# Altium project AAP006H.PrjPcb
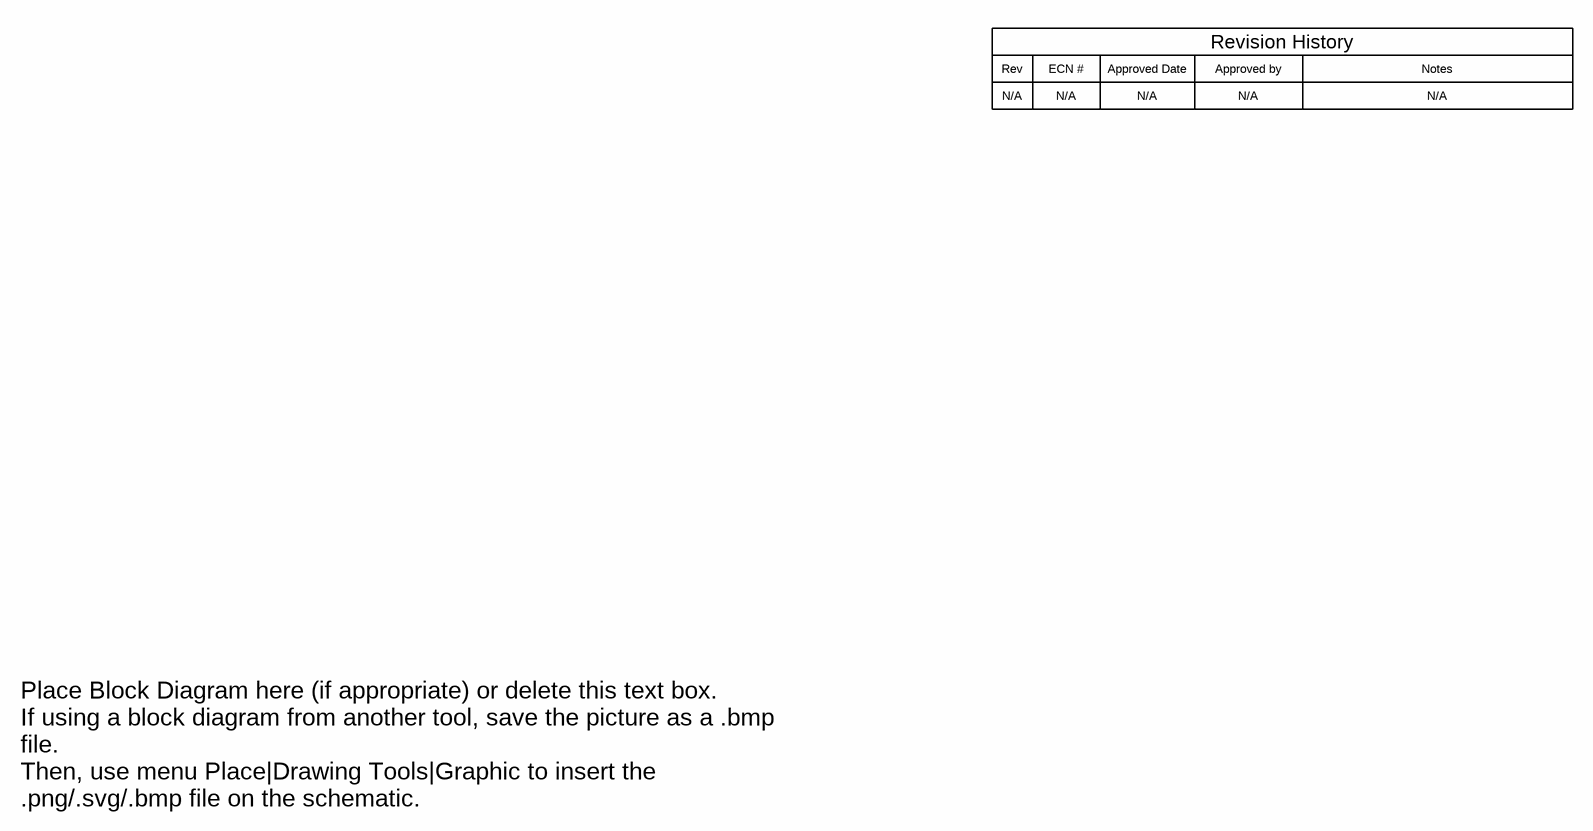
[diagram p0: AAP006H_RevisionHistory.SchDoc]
EVM_Orderable: PP-CMB-EVM; TID: N/A; TechSupport: http://www.ti.com/support; SCH_Rev: H; PRJ_Title: Pure Path Console MotherBoard; PRJ_Number: AAP006; PRJ_Engineer: CODY DOWLING; PRJ_Customer: Public Release; PCB_Rev: H; PCB_Layout: LDN; CopyrightYear: 2017
13 sheets, 94 parts. Net scope: flat (ports and power ports of the same name join across sheets).
Board file: AAP006H_PCB.PcbDoc
Sheets:
  AAP006H_RevisionHistory.SchDoc
  AAP006H_BlockDiagram.SchDoc
  AAP006H_USB.SchDoc
  AAP006H_SPDIF.SchDoc
  AAP006H_Codec1_PCM3168A.SchDoc
  AAP006H_Codec2_AIC3262.SchDoc
  AAP006H_PWM-Modulator.SchDoc
  AAP006H_MSP430.SchDoc
  AAP006H_IO-Expander.SchDoc
  AAP006H_MainConnector.SchDoc
  AAP006H_PowerSupplies.SchDoc
  AAP006H_StandoffHardware.SchDoc
  AAP006H_EVM_Hardware.SchDoc

## Sheet AAP006H_RevisionHistory.SchDoc
size 431 x 279 mm; Date: Not shown in title block; ApprovedBy: Not shown in title block; CheckedBy: Not shown in title block; Author: Not shown in title block; CompanyName: Not shown in title block; Engineer: Not shown in title block; Organization: Not shown in title block; Address1: Not shown in title block; Address2: Not shown in title block; Address3: Not shown in title block; Address4: Not shown in title block; DocumentNumber: 1; Revision: Use project parameter SCH_Rev; SheetNumber: 1; SheetTotal: 13; PageSetup: Record=PageOptions¦CenterHorizontal=True¦CenterVertical=True¦PrintScale=1.00¦XCorrection=1.00¦YCorrection=1.00¦PrintKind=0¦BorderSize=5000000¦LeftOffset=0¦BottomOffset=0¦Orientation=2¦PaperLength=1000¦PaperWidth=1000¦Scale=100¦PaperSource=15¦PrintQuality=600¦MediaType=1¦DitherType=10¦PaperKind=Letter¦PrintScaleMode=1

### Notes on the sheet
- Rev
- N/A
- ECN #
- Approved Date
- Approved by
- Revision History
- Notes
- Place Block Diagram here (if appropriate) or delete this text box.
  If using a block diagram from another tool, save the picture as a .bmp file.
  Then, use menu Place|Drawing Tools|Graphic to insert the .png/.svg/.bmp file on the schematic.

## Sheet AAP006H_BlockDiagram.SchDoc
size 431 x 279 mm; Date: Not shown in title block; ApprovedBy: Not shown in title block; CheckedBy: Not shown in title block; Author: Not shown in title block; CompanyName: Not shown in title block; Engineer: Not shown in title block; Organization: Not shown in title block; Address1: Not shown in title block; Address2: Not shown in title block; Address3: Not shown in title block; Address4: Not shown in title block; DocumentNumber: 2; Revision: Use project parameter SCH_Rev; SheetNumber: 2; SheetTotal: 13; PageSetup: Record=PageOptions¦CenterHorizontal=True¦CenterVertical=True¦PrintScale=1.00¦XCorrection=1.00¦YCorrection=1.00¦PrintKind=0¦BorderSize=5000000¦LeftOffset=0¦BottomOffset=0¦Orientation=2¦PaperLength=1000¦PaperWidth=1000¦Scale=100¦PaperSource=15¦PrintQuality=600¦MediaType=1¦DitherType=10¦PaperKind=Letter¦PrintScaleMode=1
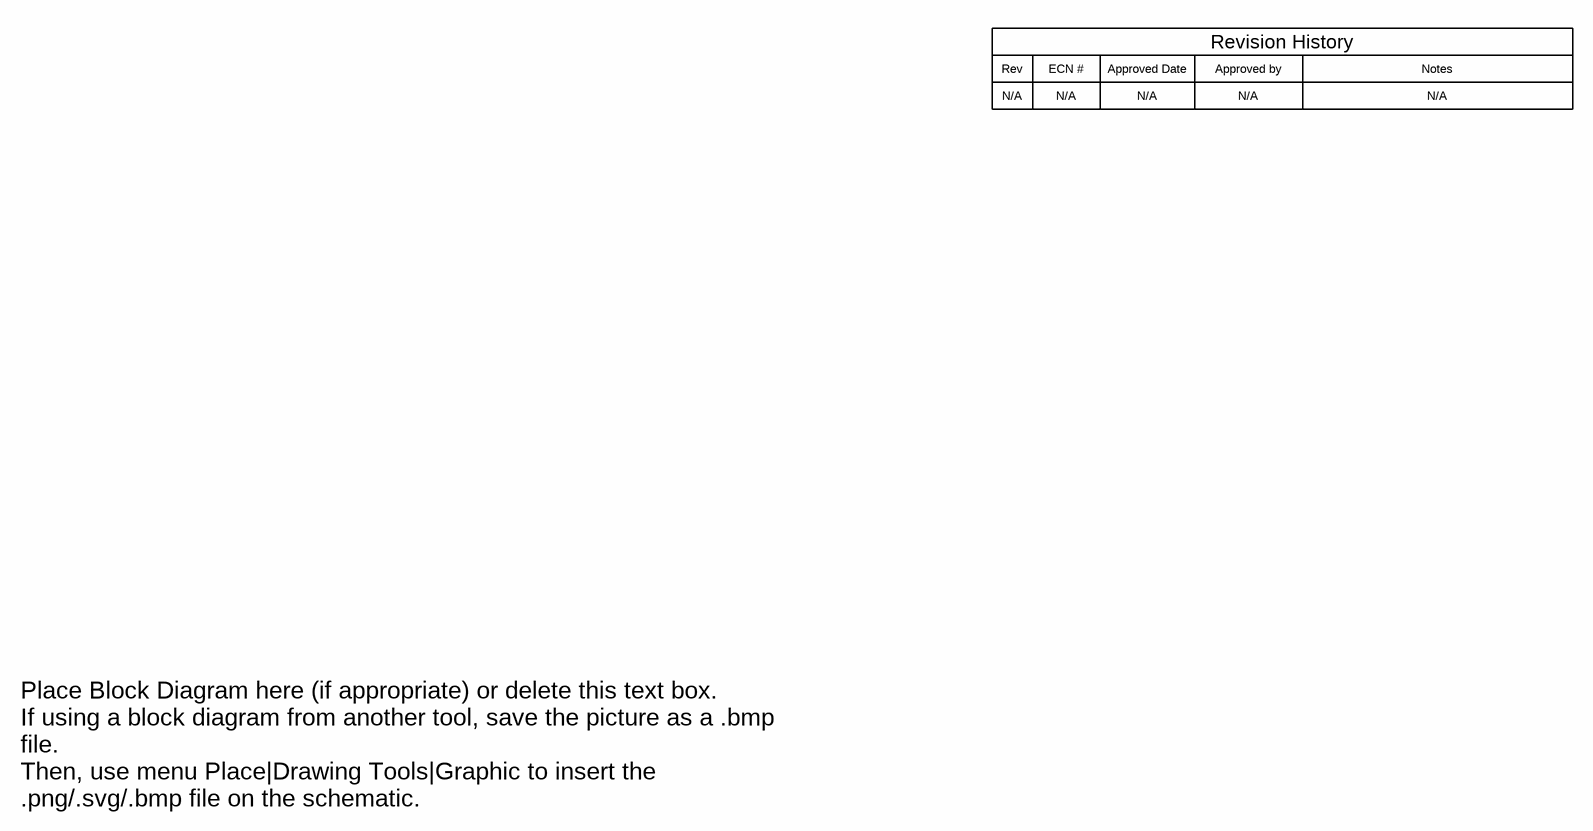
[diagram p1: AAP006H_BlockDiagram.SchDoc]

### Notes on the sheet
- Rev
- N/A
- ECN #
- Approved Date
- Approved by
- Revision History
- Notes
- Place Block Diagram here (if appropriate) or delete this text box.
  If using a block diagram from another tool, save the picture as a .bmp file.
  Then, use menu Place|Drawing Tools|Graphic to insert the .png/.svg/.bmp file on the schematic.

## Sheet AAP006H_USB.SchDoc: USB I/O
size 538 x 342 mm; Date: Not shown in title block; ApprovedBy: Not shown in title block; CheckedBy: Not shown in title block; Author: Not shown in title block; CompanyName: Not shown in title block; DrawnBy: LDN; Engineer: Not shown in title block; Organization: Not shown in title block; Address1: Not shown in title block; Address2: Not shown in title block; Address3: Not shown in title block; Address4: Not shown in title block; DocumentNumber: 3; Revision: Use project parameter SCH_Rev; SheetNumber: 3; SheetTotal: 13; PageSetup: Record=PageOptions¦CenterHorizontal=True¦CenterVertical=True¦PrintScale=1.00¦XCorrection=1.00¦YCorrection=1.00¦PrintKind=0¦BorderSize=5000000¦LeftOffset=0¦BottomOffset=0¦Orientation=2¦PaperLength=1000¦PaperWidth=1000¦Scale=100¦PaperSource=15¦PrintQuality=600¦MediaType=1¦DitherType=10¦PaperKind=Letter¦PrintScaleMode=1
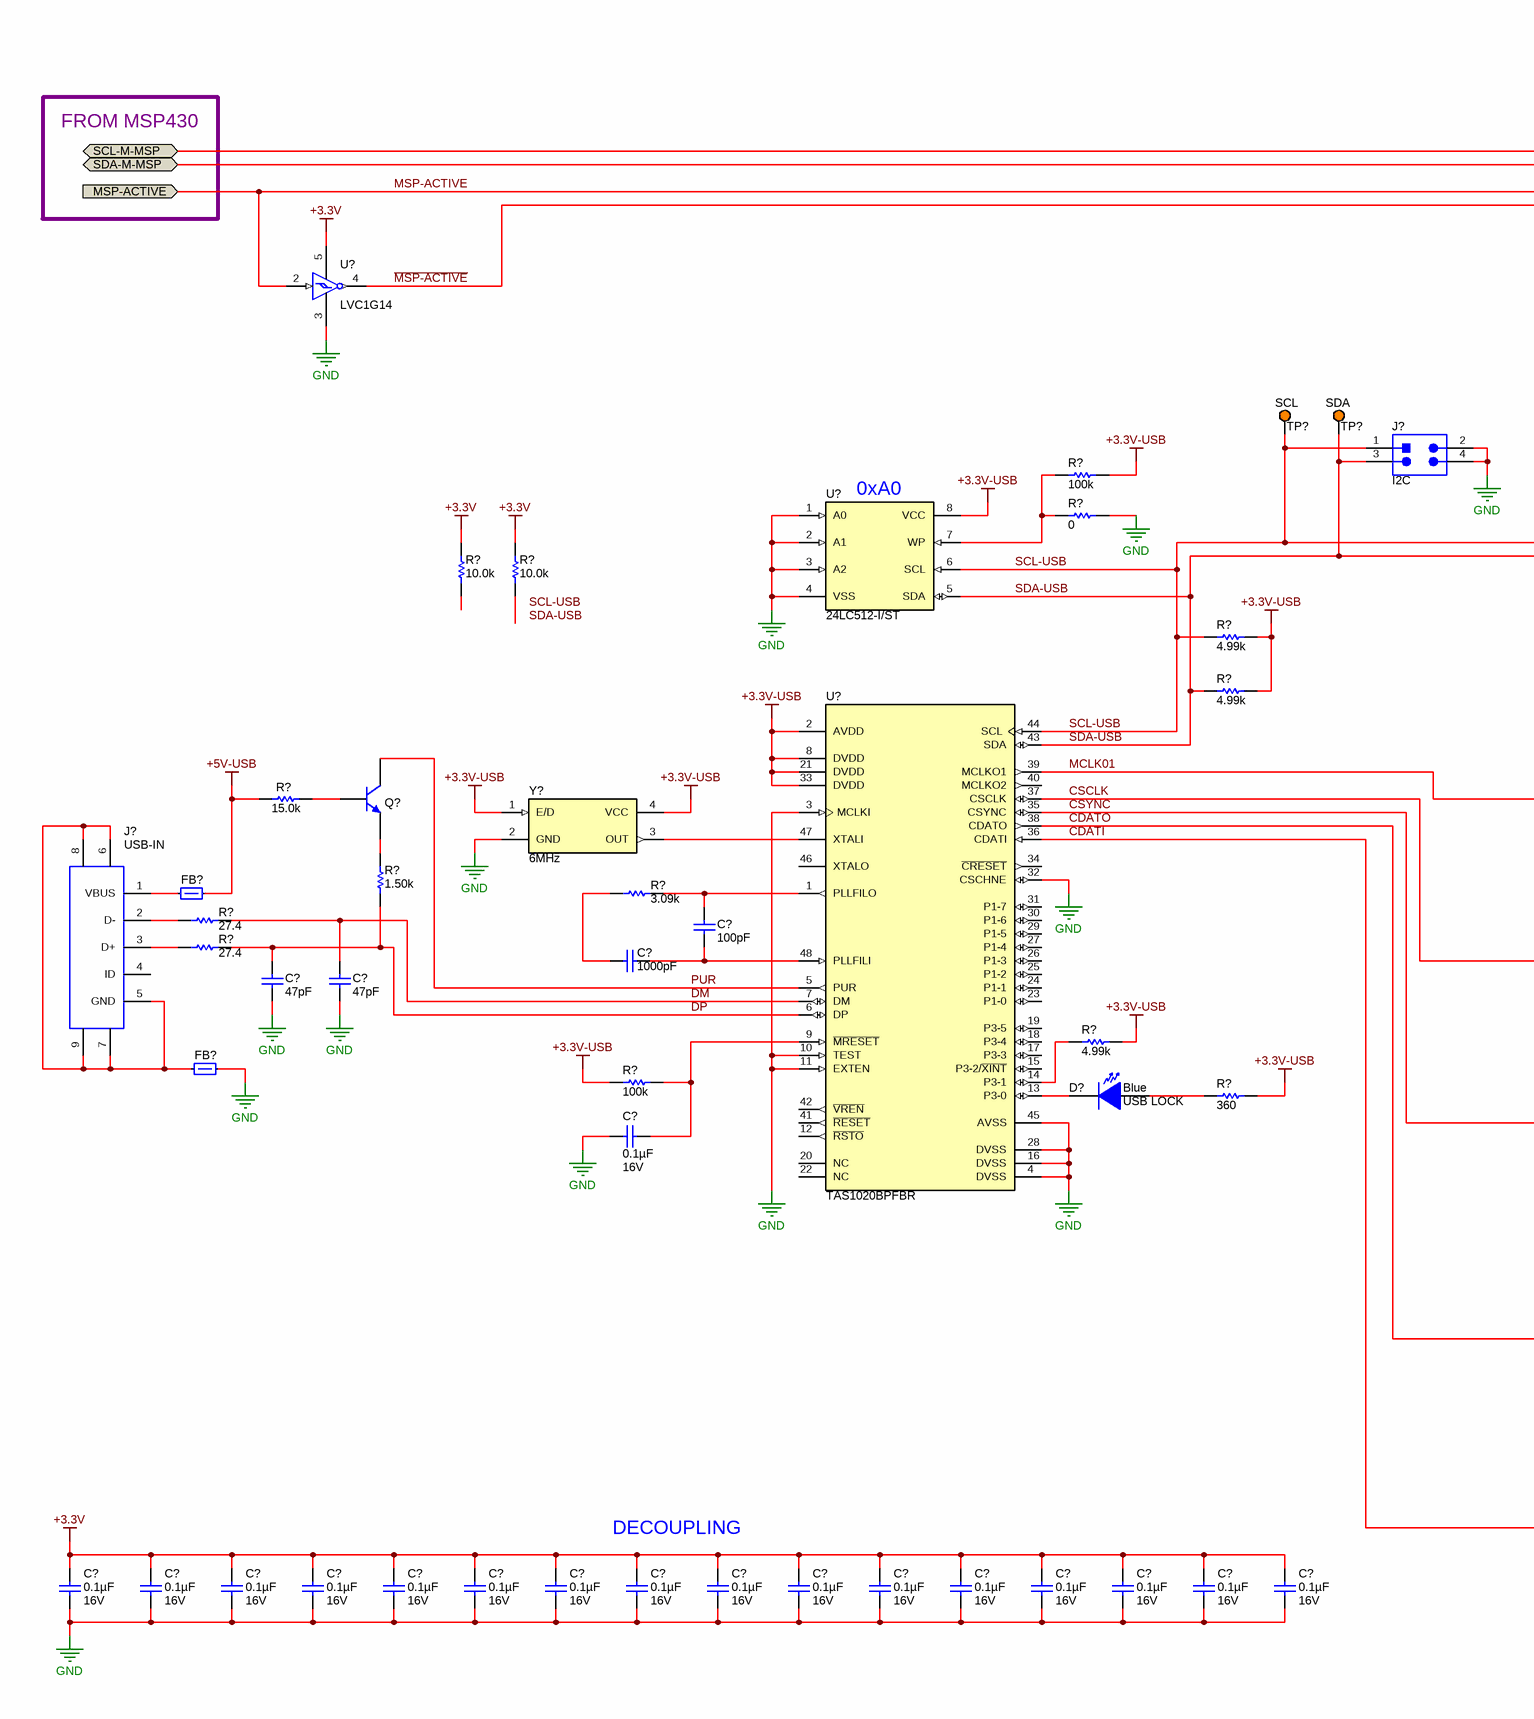
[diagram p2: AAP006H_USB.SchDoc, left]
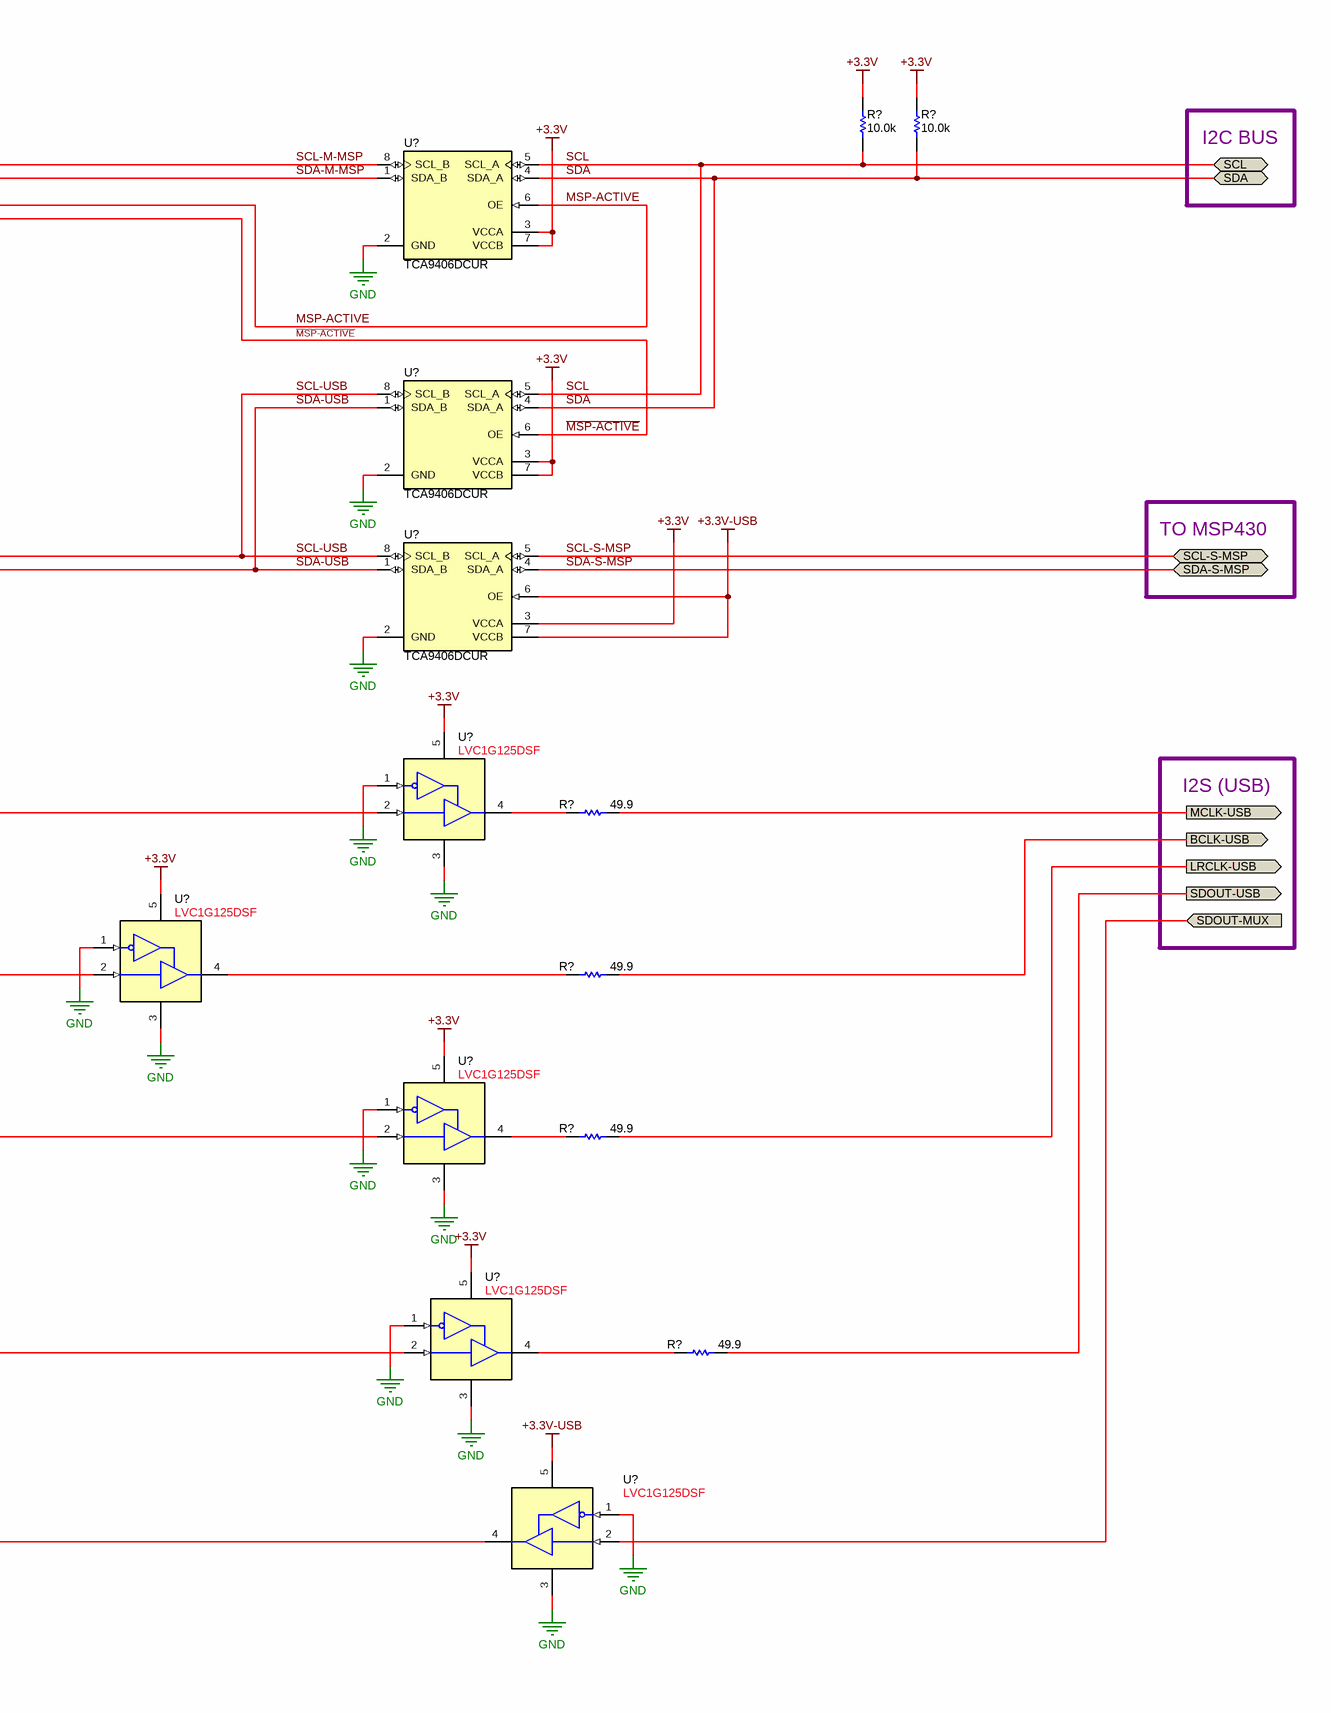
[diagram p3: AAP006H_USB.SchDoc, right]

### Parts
(Parts that share a designator on the sheet are numbered #1, #2 ... from top to bottom, then left to right.)
C?#1  ValueDisplayed: 100pF  [0402L]  (hidden comment: GRM1555C1H101JA01D)
C?#2  ValueDisplayed: 1000pF  [0402L]  (hidden comment: GRM1555C1H102JA01D)
C?#3  ValueDisplayed: 47pF  [0402L]  (hidden comment: GRM1555C1E470JA01D)
C?#4  ValueDisplayed: 47pF  [0402L]  (hidden comment: GRM1555C1E470JA01D)
C?#5  ValueDisplayed: 0.1µF  Value2: 16V  [0402L]  (hidden comment: GRM155R71C104KA88D)
C?#6  ValueDisplayed: 0.1µF  Value2: 16V  [0402L]  (hidden comment: GRM155R71C104KA88D)
C?#7  ValueDisplayed: 0.1µF  Value2: 16V  [0402L]  (hidden comment: GRM155R71C104KA88D)
C?#8  ValueDisplayed: 0.1µF  Value2: 16V  [0402L]  (hidden comment: GRM155R71C104KA88D)
C?#9  ValueDisplayed: 0.1µF  Value2: 16V  [0402L]  (hidden comment: GRM155R71C104KA88D)
C?#10  ValueDisplayed: 0.1µF  Value2: 16V  [0402L]  (hidden comment: GRM155R71C104KA88D)
C?#11  ValueDisplayed: 0.1µF  Value2: 16V  [0402L]  (hidden comment: GRM155R71C104KA88D)
C?#12  ValueDisplayed: 0.1µF  Value2: 16V  [0402L]  (hidden comment: GRM155R71C104KA88D)
C?#13  ValueDisplayed: 0.1µF  Value2: 16V  [0402L]  (hidden comment: GRM155R71C104KA88D)
C?#14  ValueDisplayed: 0.1µF  Value2: 16V  [0402L]  (hidden comment: GRM155R71C104KA88D)
C?#15  ValueDisplayed: 0.1µF  Value2: 16V  [0402L]  (hidden comment: GRM155R71C104KA88D)
C?#16  ValueDisplayed: 0.1µF  Value2: 16V  [0402L]  (hidden comment: GRM155R71C104KA88D)
C?#17  ValueDisplayed: 0.1µF  Value2: 16V  [0402L]  (hidden comment: GRM155R71C104KA88D)
C?#18  ValueDisplayed: 0.1µF  Value2: 16V  [0402L]  (hidden comment: GRM155R71C104KA88D)
C?#19  ValueDisplayed: 0.1µF  Value2: 16V  [0402L]  (hidden comment: GRM155R71C104KA88D)
C?#20  ValueDisplayed: 0.1µF  Value2: 16V  [0402L]  (hidden comment: GRM155R71C104KA88D)
C?#21  ValueDisplayed: 0.1µF  Value2: 16V  [0402L]  (hidden comment: GRM155R71C104KA88D)
D?  USB LOCK  value Blue  [LED_SMLP12_BLUE]
FB?#1  MPZ1608S221A  [0603L]  (value not drawn)
FB?#2  MPZ1608S221A  [0603L]  (value not drawn)
J?#1  I2C  [Sullins_PxC02DAAN]
J?#2  USB-IN  [CONN_USB_DX4R205JJA]
Q?  MMBT2222A  [SOT-23]  (value not drawn)
R?#1  value 10.0k  [0402L]  (hidden comment: CRCW040210K0FKED)
R?#2  value 10.0k  [0402L]  (hidden comment: CRCW040210K0FKED)
R?#3  value 100k  [0402L]  (hidden comment: CRCW0402100KFKED)
R?#4  ValueDisplayed: 0  [0603L]  (hidden comment: CRCW06030000Z0EA)
R?#5  ValueDisplayed: 10.0k  [0402L]  (hidden comment: CRCW040210K0FKED)
R?#6  ValueDisplayed: 10.0k  [0402L]  (hidden comment: CRCW040210K0FKED)
R?#7  value 4.99k  [0402L]  (hidden comment: CRCW04024K99FKED)
R?#8  value 4.99k  [0402L]  (hidden comment: CRCW04024K99FKED)
R?#9  value 15.0k  [0402L]  (hidden comment: CRCW040215K0FKED)
R?#10  value 49.9  [0402L]  (hidden comment: CRCW040249R9FKED)
R?#11  value 1.50k  [0402L]  (hidden comment: CRCW04021K50FKED)
R?#12  value 3.09k  [0402L]  (hidden comment: CRCW04023K09FKED)
R?#13  value 27.4  [0402L]  (hidden comment: CRCW040227R4FKED)
R?#14  value 27.4  [0402L]  (hidden comment: CRCW040227R4FKED)
R?#15  value 49.9  [0402L]  (hidden comment: CRCW040249R9FKED)
R?#16  value 4.99k  [0402L]  (hidden comment: CRCW04024K99FKED)
R?#17  value 100k  [0402L]  (hidden comment: CRCW0402100KFKED)
R?#18  value 360  [0402L]  (hidden comment: CRCW0402360RJNED)
R?#19  value 49.9  [0402L]  (hidden comment: CRCW040249R9FKED)
R?#20  value 49.9  [0402L]  (hidden comment: CRCW040249R9FKED)
TP?#1  SCL  [Keystone5003]
TP?#2  SDA  [Keystone5003]
U?#1  TCA9406DCUR  [DCU0008A_N]
U?#2  LVC1G14  [DRL0005A]
U?#3  TCA9406DCUR  [DCU0008A_N]
U?#4  TCA9406DCUR  [DCU0008A_N]
U?#5  24LC512-I/ST  [TSSOP-8]
U?#6  NewPartNumber: LVC1G125DSF  [DRL0005A]  (hidden comment: SN74LVC1G125DRLR)
U?#7  TAS1020BPFBR  [PFB0048A_N]
U?#8  NewPartNumber: LVC1G125DSF  [DRL0005A]  (hidden comment: SN74LVC1G125DRLR)
U?#9  NewPartNumber: LVC1G125DSF  [DRL0005A]  (hidden comment: SN74LVC1G125DRLR)
U?#10  NewPartNumber: LVC1G125DSF  [DRL0005A]  (hidden comment: SN74LVC1G125DRLR)
U?#11  NewPartNumber: LVC1G125DSF  [DRL0005A]  (hidden comment: SN74LVC1G125DRLR)
Y?  Frequency: 6MHz  [OSC_CTS_625]  (hidden comment: 625L3I006M00000)

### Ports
BCLK-USB (out), LRCLK-USB (out), MCLK-USB (out), MSP-ACTIVE (in), SCL (bidir), SCL-M-MSP (bidir), SCL-S-MSP (bidir), SDA (bidir), SDA-M-MSP (bidir), SDA-S-MSP (bidir), SDOUT-MUX (in), SDOUT-USB (out)

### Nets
+3.3V: C?#6.1 C?#7.1 C?#8.1 C?#9.1 C?#10.1 C?#11.1 C?#12.1 C?#13.1 C?#14.1 C?#15.1 C?#16.1 C?#17.1 C?#18.1 C?#19.1 C?#20.1 C?#21.1 R?#1.1 R?#2.1 R?#5.2 R?#6.2 U?#1.3(VCCA) U?#1.7(VCCB) U?#2.5(VCC) U?#3.3(VCCA) U?#3.7(VCCB) U?#4.3(VCCA) U?#6.5(VCC) U?#8.5(VCC) U?#9.5(VCC) U?#10.5(VCC)
+3.3V-USB: R?#3.2 R?#7.2 R?#8.2 R?#16.1 R?#17.1 R?#18.1 U?#4.6(OE) U?#4.7(VCCB) U?#5.8(VCC) U?#7.2(AVDD) U?#7.8(DVDD) U?#7.21(DVDD) U?#7.33(DVDD) U?#11.5(VCC) Y?.1(E/D) Y?.4(VCC)
+5V-USB: FB?#1.2 R?#9.1
GND: C?#3.1 C?#4.1 C?#5.1 C?#6.2 C?#7.2 C?#8.2 C?#9.2 C?#10.2 C?#11.2 C?#12.2 C?#13.2 C?#14.2 C?#15.2 C?#16.2 C?#17.2 C?#18.2 C?#19.2 C?#20.2 C?#21.2 FB?#2.2 J?#1.2 J?#1.4 R?#4.2 U?#1.2(GND) U?#2.3(GND) U?#3.2(GND) U?#4.2(GND) U?#5.1(A0) U?#5.2(A1) U?#5.3(A2) U?#5.4(VSS) U?#6.1(~{OE}) U?#6.3(GND) U?#7.3(MCLKI) U?#7.4(DVSS) U?#7.10(TEST) U?#7.11(EXTEN) U?#7.16(DVSS) U?#7.28(DVSS) U?#7.32(CSCHNE) U?#7.45(AVSS) U?#8.1(~{OE}) U?#8.3(GND) U?#9.1(~{OE}) U?#9.3(GND) U?#10.1(~{OE}) U?#10.3(GND) U?#11.1(~{OE}) U?#11.3(GND) Y?.2(GND)
~{MSP-ACTIVE}: U?#2.4(Y) U?#3.6(OE)
BCLK-USB: R?#15.2 ; port BCLK-USB
CDATI: U?#7.36(CDATI) U?#11.4(Y)
CDATO: U?#7.38(CDATO) U?#10.2(A)
CSCLK: U?#7.37(CSCLK) U?#8.2(A)
CSYNC: U?#7.35(CSYNC) U?#9.2(A)
DM: C?#4.2 R?#13.2 U?#7.7(DM)
DP: C?#3.2 R?#11.2 R?#14.2 U?#7.6(DP)
LRCLK-USB: R?#19.2 ; port LRCLK-USB
MCLK01: U?#6.2(A) U?#7.39(MCLKO1)
MCLK-USB: R?#10.2 ; port MCLK-USB
MSP-ACTIVE: U?#1.6(OE) U?#2.2(A) ; port MSP-ACTIVE
PUR: Q?.3(C) U?#7.5(PUR)
SCL: R?#1.2 U?#1.5(SCL_A) U?#3.5(SCL_A) ; port SCL
SCL-M-MSP: U?#1.8(SCL_B) ; port SCL-M-MSP
SCL-S-MSP: U?#4.5(SCL_A) ; port SCL-S-MSP
SCL-USB: J?#1.1 R?#7.1 TP?#1.1 U?#3.8(SCL_B) U?#4.8(SCL_B) U?#5.6(SCL) U?#7.44(SCL)
SDA: R?#2.2 U?#1.4(SDA_A) U?#3.4(SDA_A) ; port SDA
SDA-M-MSP: U?#1.1(SDA_B) ; port SDA-M-MSP
SDA-S-MSP: U?#4.4(SDA_A) ; port SDA-S-MSP
SDA-USB: J?#1.3 R?#8.1 TP?#2.1 U?#3.1(SDA_B) U?#4.1(SDA_B) U?#5.5(SDA) U?#7.43(SDA)
SDOUT-MUX: U?#11.2(A) ; port SDOUT-MUX
SDOUT-USB: R?#20.2 ; port SDOUT-USB
NetC?#1_1: C?#1.1 R?#12.2 U?#7.1(PLLFILO)
NetC?#1_2: C?#1.2 C?#2.1 U?#7.48(PLLFILI)
NetC?#2_2: C?#2.2 R?#12.1
NetC?#5_2: C?#5.2 R?#17.2 U?#7.9(~{MRESET})
NetD?_1: D?.1(A) R?#18.2
NetD?_2: D?.2(K) U?#7.13(P3-0)
NetFB?#1_1: FB?#1.1 J?#2.1(VBUS)
NetFB?#2_1: FB?#2.1 J?#2.5(GND) J?#2.6 J?#2.7 J?#2.8 J?#2.9
NetJ?#2_2: J?#2.2(D-) R?#13.1
NetJ?#2_3: J?#2.3(D+) R?#14.1
NetQ?_1: Q?.1(B) R?#9.2
NetQ?_2: Q?.2(E) R?#11.1
NetR?#3_1: R?#3.1 R?#4.1 U?#5.7(WP)
NetR?#10_1: R?#10.1 U?#6.4(Y)
NetR?#15_1: R?#15.1 U?#8.4(Y)
NetR?#16_2: R?#16.2 U?#7.14(P3-1)
NetR?#19_1: R?#19.1 U?#9.4(Y)
NetR?#20_1: R?#20.1 U?#10.4(Y)
NetU?#7_47: U?#7.47(XTALI) Y?.3(OUT)

Not connected (* = marked no-connect by the designer): J?#2 4(ID); R?#5 1; R?#6 1; U?#7 12(~{RSTO}) 15(P3-2/~{XINT}) 17(P3-3) 18(P3-4) 19(P3-5) 20(NC) 22(NC) 23(P1-0) 24(P1-1) 25(P1-2) 26(P1-3) 27(P1-4) 29(P1-5) 30(P1-6) 31(P1-7) 34(~{CRESET}) 40(MCLKO2) 41(~{RESET}) 42(~{VREN}) 46(XTALO)

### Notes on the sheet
- FROM MSP430
- I2C BUS
- (near U?#5) 0xA0
- TO MSP430
- I2S (USB)
- (near C?#13) DECOUPLING
- Labels drawn without touching a wire or pin: SCL-USB, SDA-USB

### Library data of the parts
C?#1 = GRM1555C1H101JA01D: CAP, CERM, 100pF, 50V, +/-5%, C0G/NP0, 0402; Manufacturer: MuRata; Polarized: N; CompType: Capacitor; U/M: EA; Cap_F: 0.0000000001; Tolerance_%: 5; Value1: Unknown; VDC_V: 50; TaMin_C: -55; TaMax_C: 125; Cap_Case: 0402
C?#2 = GRM1555C1H102JA01D: CAP, CERM, 1000pF, 50V, +/-5%, C0G/NP0, 0402; Manufacturer: MuRata; Polarized: N; CompType: Capacitor; U/M: EA; Cap_F: 0.000000001; Tolerance_%: 5; Value1: Unknown; VDC_V: 50; TaMin_C: -55; TaMax_C: 125; Cap_Case: 0402
C?#3 C?#4 = GRM1555C1E470JA01D: CAP, CERM, 47pF, 25V, +/-5%, C0G/NP0, 0402; Manufacturer: MuRata; Polarized: N; CompType: Capacitor; U/M: EA; Cap_F: 0.000000000047; Tolerance_%: 5; Value1: Unknown; VDC_V: 25; TaMin_C: -55; TaMax_C: 125; Cap_Case: 0402
C?#5-C?#21 = GRM155R71C104KA88D: CAP, CERM, 0.1uF, 16V, +/-10%, X7R, 0402; Manufacturer: MuRata; Polarized: N; CompType: Capacitor; U/M: EA; Cap_F: 0.0000001; Tolerance_%: 10; Value1: Unknown; VDC_V: 16; TaMin_C: -55; TaMax_C: 125; Cap_Case: 0402
D? = SMLP12BC7TT86: LED, Blue, SMD; Manufacturer: Rohm; Type: InGaN; Vf_V: 2.9; Value2: 2.9V; Io_A: 0.005; Tjmax_C: 85; Value1: W; U/M: EA
FB?#1 FB?#2 = MPZ1608S221A: 2.2A Ferrite Bead, 220 ohm @ 100MHz, SMD; Manufacturer: TDK; Value: 220 ohm; Imax_A: 2.2; DCR_ohm: 0.05; Value1: 0.05 ohm; ZTyp@100MHz_Ohm: 220; U/M: EA
J?#1 = PBC02DAAN: Header, 2.54mm, 2x2, Gold, TH; Manufacturer: Sullins Connector Solutions; SymbolCreator: a0412235; Pitch_mm: 2.54; Gender: Male; Shrouded: N; Row_Count: 2; Current_A: 3; Voltage_V: 1800; Cert_UL: Y
J?#2 = DX4R205JJAR1800: Connector, Receptacle, Micro-USB Type AB, R/A, Bottom Mount SMT; Manufacturer: JAE Electronics; SymbolCreator: a0799628; U/M: EA
Q? = MMBT2222A, Fairchild Semiconductor: Transistor, NPN, 40V, 0.15A, SOT-23; CompType: BJT; PNP: 0; NPN: 1; Vceo_V: 40; Vcesat1_V: 0.3; Value: 0.3V; IcRated_A: 0.15; HfeMax: 300; TaMin_C: -55; TaMax_C: 150; U/M: EA
R?#1 R?#2 = CRCW040210K0FKED: RES, 10.0k ohm, 1%, 0.063W, 0402; Manufacturer: Vishay-Dale; CompType: Resistor; Res_ohm: 10000; Value_Code: 10k0; Tolerance_%: 1; Power_W: 0.063; VDC_V: 50; TempCo: 100 ppm/C; EIA_Code: E96; U/M: EA
R?#3 R?#17 = CRCW0402100KFKED: RES, 100k ohm, 1%, 0.063W, 0402; Manufacturer: Vishay-Dale; CompType: Resistor; Res_ohm: 100000; Tolerance_%: 1; Power_W: 0.063; VDC_V: 50; TempCo: 100 ppm/C; EIA_Code: E96; U/M: EA
R?#4 = CRCW06030000Z0EA: RES, 0, 5%, 0.1 W, 0603; Manufacturer: Vishay-Dale; CompType: Resistor; Value: 0; Value_Code: 0000; Tolerance_%: 5; Power_W: 0.1; Value2: 0.1W; VDC_V: 75; TempCo: 200 ppm/C; EIA_Code: E24; U/M: EA
R?#5 R?#6 = CRCW040210K0FKED: RES, 10.0 k, 1%, 0.063 W, 0402; Manufacturer: Vishay-Dale; CompType: Resistor; Value: 10.0k; Res_ohm: 10000; Value_Code: 10k0; Tolerance_%: 1; Power_W: 0.063; Value2: 0.063W; VDC_V: 50; TempCo: 100 ppm/C; EIA_Code: E96; U/M: EA
R?#7 R?#8 R?#16 = CRCW04024K99FKED: RES, 4.99k ohm, 1%, 0.063W, 0402; Manufacturer: Vishay-Dale; CompType: Resistor; Res_ohm: 4990; Value_Code: 4k99; Tolerance_%: 1; Power_W: 0.063; VDC_V: 50; TempCo: 100 ppm/C; EIA_Code: E96; U/M: EA
R?#9 = CRCW040215K0FKED: RES, 15.0k ohm, 1%, 0.063W, 0402; Manufacturer: Vishay-Dale; CompType: Resistor; Res_ohm: 15000; Value_Code: 15k0; Tolerance_%: 1; Power_W: 0.063; VDC_V: 50; TempCo: 100 ppm/C; EIA_Code: E96; U/M: EA
R?#10 R?#15 R?#19 R?#20 = CRCW040249R9FKED: RES, 49.9 ohm, 1%, 0.063W, 0402; Manufacturer: Vishay-Dale; CompType: Resistor; Value_Code: 49R9; Tolerance_%: 1; Power_W: 0.063; VDC_V: 50; TempCo: 100 ppm/C; EIA_Code: E96; U/M: EA
R?#11 = CRCW04021K50FKED: RES, 1.50k ohm, 1%, 0.063W, 0402; Manufacturer: Vishay-Dale; CompType: Resistor; Res_ohm: 1500; Value_Code: 1k50; Tolerance_%: 1; Power_W: 0.063; VDC_V: 50; TempCo: 100 ppm/C; EIA_Code: E96; U/M: EA
R?#12 = CRCW04023K09FKED: RES, 3.09k ohm, 1%, 0.063W, 0402; Manufacturer: Vishay-Dale; CompType: Resistor; Res_ohm: 3090; Value_Code: 3k09; Tolerance_%: 1; Power_W: 0.063; VDC_V: 50; TempCo: 100 ppm/C; EIA_Code: E96; U/M: EA
R?#13 R?#14 = CRCW040227R4FKED: RES, 27.4 ohm, 1%, 0.063W, 0402; Manufacturer: Vishay-Dale; CompType: Resistor; Value_Code: 27R4; Tolerance_%: 1; Power_W: 0.063; VDC_V: 50; TempCo: 100 ppm/C; EIA_Code: E96; U/M: EA
R?#18 = CRCW0402360RJNED: RES, 360 ohm, 5%, 0.063W, 0402; Manufacturer: Vishay-Dale; CompType: Resistor; Value_Code: 360R; Tolerance_%: 5; Power_W: 0.063; VDC_V: 50; TempCo: 200 ppm/C; EIA_Code: E24; U/M: EA
TP?#1 TP?#2 = 5003: Test Point, Miniature, Orange, TH; Manufacturer: Keystone; CompType: Test Point Loop; U/M: EA
U?#1 U?#3 U?#4 = TCA9406DCUR: TCA9406 Dual Bidirectional 1-MHz I2C-BUS and SMBus Voltage Level-Translator, 1.65 to 3.6 V, -40 to 85 degC, 8-pin US8 (DCU), Green (RoHS & no Sb/Br); Manufacturer: Texas Instruments; Alternate PartNumber: Equivalent; SubFamily: I2C Special Function; No. of Outputs: 2; VCC(Min)(V): -0.5; VCC(Max)(V): 4.6; Max Frequency(kHz): 1000; Function: I2C Voltage Level Translator; Enable Pin: Yes; Rating: Catalog
U?#2 = SN74LVC1G14DRLR: SINGLE SCHMITT-TRIGGER INVERTER, DRL0005A (SOT-5); Manufacturer: Texas Instruments; SymbolCreator: a0799628; SizeArea_mm2: 2.56; SizeAreaWB_mm2: 6.76; SizeX_mm: 1.6; SizeZ_mm: 0.6; CompType: IC; U/M: EA
U?#5 = 24LC512-I/ST: EEPROM, 512KBIT, 400KHZ, 8TSSOP; Manufacturer: Microchip; SymbolCreator: a0411947; SizeAreaWB_mm2: 42; SizeArea_mm2: 19.2; SizeX_mm: 6.4; SizeY_mm: 3; SizeZ_mm: 1.2
U?#6 U?#8-U?#11 = SN74LVC1G125DRLR: Single Bus Buffer Gate With 3-State Output, DRL0005A (SOT-5); Manufacturer: Texas Instruments; SymbolCreator: Altium; SizeArea_mm2: 2.56; SizeAreaWB_mm2: 6.76; SizeX_mm: 1.6; SizeZ_mm: 0.6; CompType: IC; U/M: EA
U?#7 = TAS1020BPFBR: USB Streaming Controller, PFB0048A, NRND; Manufacturer: Texas Instruments; SymbolCreator: Altium; CompType: IC; U/M: EA
Y? = 625L3I006M00000: Oscillator, 6MHz, 3.3V, SMD; Manufacturer: CTS Electrocomponents; SymbolCreator: a0411947; U/M: EA; TaMin_C: -40; TaMax_C: 85; Frequency Stability: ±50ppm

## Sheet AAP006H_SPDIF.SchDoc
size 431 x 279 mm; Date: Not shown in title block; ApprovedBy: Not shown in title block; CheckedBy: Not shown in title block; Author: Not shown in title block; CompanyName: Not shown in title block; Engineer: Not shown in title block; Organization: Not shown in title block; Address1: Not shown in title block; Address2: Not shown in title block; Address3: Not shown in title block; Address4: Not shown in title block; DocumentNumber: 4; Revision: Use project parameter SCH_Rev; SheetNumber: 4; SheetTotal: 13; PageSetup: Record=PageOptions¦CenterHorizontal=True¦CenterVertical=True¦PrintScale=1.00¦XCorrection=1.00¦YCorrection=1.00¦PrintKind=0¦BorderSize=5000000¦LeftOffset=0¦BottomOffset=0¦Orientation=2¦PaperLength=1000¦PaperWidth=1000¦Scale=100¦PaperSource=15¦PrintQuality=600¦MediaType=1¦DitherType=10¦PaperKind=Letter¦PrintScaleMode=1
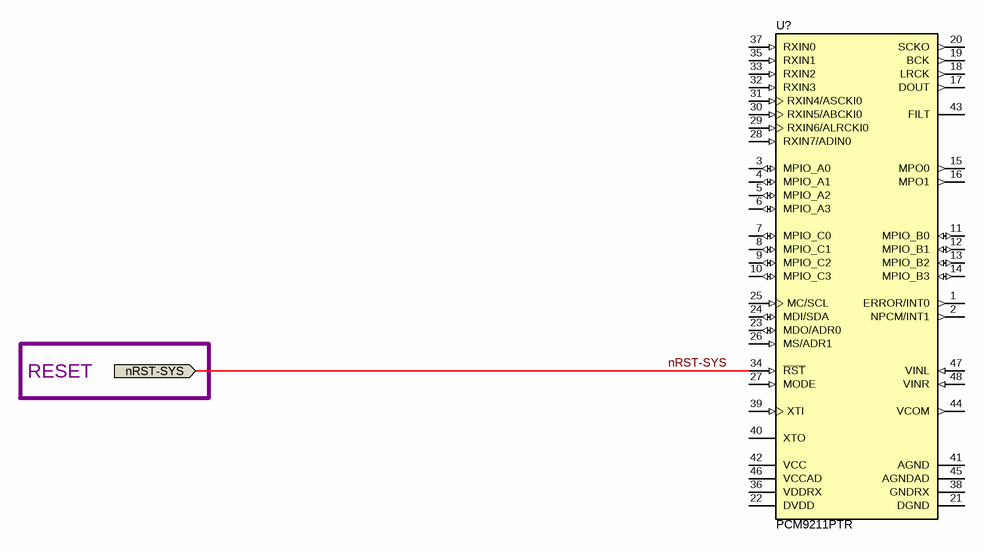
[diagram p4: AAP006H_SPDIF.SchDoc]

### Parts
(Parts that share a designator on the sheet are numbered #1, #2 ... from top to bottom, then left to right.)
U?#12  PCM9211PTR  [PT0048A_N]

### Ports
nRST-SYS (in)

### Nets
nRST-SYS: U?#12.34(~{RST}) ; port nRST-SYS

Not connected (* = marked no-connect by the designer): U?#12 1(ERROR/INT0) 2(NPCM/INT1) 3(MPIO_A0) 4(MPIO_A1) 5(MPIO_A2) 6(MPIO_A3) 7(MPIO_C0) 8(MPIO_C1) 9(MPIO_C2) 10(MPIO_C3) 11(MPIO_B0) 12(MPIO_B1) 13(MPIO_B2) 14(MPIO_B3) 15(MPO0) 16(MPO1) 17(DOUT) 18(LRCK) 19(BCK) 20(SCKO) 21(DGND) 22(DVDD) 23(MDO/ADR0) 24(MDI/SDA) 25(MC/SCL) 26(MS/ADR1) 27(MODE) 28(RXIN7/ADIN0) 29(RXIN6/ALRCKI0) 30(RXIN5/ABCKI0) 31(RXIN4/ASCKI0) 32(RXIN3) 33(RXIN2) 35(RXIN1) 36(VDDRX) 37(RXIN0) 38(GNDRX) 39(XTI) 40(XTO) 41(AGND) 42(VCC) 43(FILT) 44(VCOM) 45(AGNDAD) 46(VCCAD) 47(VINL) 48(VINR)

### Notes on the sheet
- RESET

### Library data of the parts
U?#12 = PCM9211PTR: 216 kHz Digital Audio Interface Transceiver (DIX) with Stereo ADC and Routing, PCM, S / PDIF, ADC, 4.5 - 5.5V for Analog, 2.9 - 3.6V for DIX, -40 to 85 degC, 48-Pin LQFP (PT), Green (RoHS & no Sb/Br); Manufacturer: Texas Instruments; Alternate PartNumber: Equivalent; SubFamily: Digital Audio Transceiver (Tx/Rx); ADC Sample Rate (kSPS): 96; ADC Resolution(Bits): 24; Jitter(ps): 50; Power Supply(V): 4.5-5.5 for Analog, 2.9-3.6 for DIX; Sampling Rate(Max)(kHz): 216; Control Mode: SPI, I2C, Hardware"

## Sheet AAP006H_Codec1_PCM3168A.SchDoc
size 431 x 279 mm; Date: Not shown in title block; ApprovedBy: Not shown in title block; CheckedBy: Not shown in title block; Author: Not shown in title block; CompanyName: Not shown in title block; Engineer: Not shown in title block; Organization: Not shown in title block; Address1: Not shown in title block; Address2: Not shown in title block; Address3: Not shown in title block; Address4: Not shown in title block; DocumentNumber: 5; Revision: Use project parameter SCH_Rev; SheetNumber: 5; SheetTotal: 13; PageSetup: Record=PageOptions¦CenterHorizontal=True¦CenterVertical=True¦PrintScale=1.00¦XCorrection=1.00¦YCorrection=1.00¦PrintKind=0¦BorderSize=5000000¦LeftOffset=0¦BottomOffset=0¦Orientation=2¦PaperLength=1000¦PaperWidth=1000¦Scale=100¦PaperSource=15¦PrintQuality=600¦MediaType=1¦DitherType=10¦PaperKind=Letter¦PrintScaleMode=1

## Sheet AAP006H_Codec2_AIC3262.SchDoc
size 431 x 279 mm; Date: Not shown in title block; ApprovedBy: Not shown in title block; CheckedBy: Not shown in title block; Author: Not shown in title block; CompanyName: Not shown in title block; Engineer: Not shown in title block; Organization: Not shown in title block; Address1: Not shown in title block; Address2: Not shown in title block; Address3: Not shown in title block; Address4: Not shown in title block; DocumentNumber: 6; Revision: Use project parameter SCH_Rev; SheetNumber: 6; SheetTotal: 13; PageSetup: Record=PageOptions¦CenterHorizontal=True¦CenterVertical=True¦PrintScale=1.00¦XCorrection=1.00¦YCorrection=1.00¦PrintKind=0¦BorderSize=5000000¦LeftOffset=0¦BottomOffset=0¦Orientation=2¦PaperLength=1000¦PaperWidth=1000¦Scale=100¦PaperSource=15¦PrintQuality=600¦MediaType=1¦DitherType=10¦PaperKind=Letter¦PrintScaleMode=1

## Sheet AAP006H_PWM-Modulator.SchDoc
size 431 x 279 mm; Date: Not shown in title block; ApprovedBy: Not shown in title block; CheckedBy: Not shown in title block; Author: Not shown in title block; CompanyName: Not shown in title block; Engineer: Not shown in title block; Organization: Not shown in title block; Address1: Not shown in title block; Address2: Not shown in title block; Address3: Not shown in title block; Address4: Not shown in title block; DocumentNumber: 7; Revision: Use project parameter SCH_Rev; SheetNumber: 7; SheetTotal: 13; PageSetup: Record=PageOptions¦CenterHorizontal=True¦CenterVertical=True¦PrintScale=1.00¦XCorrection=1.00¦YCorrection=1.00¦PrintKind=0¦BorderSize=5000000¦LeftOffset=0¦BottomOffset=0¦Orientation=2¦PaperLength=1000¦PaperWidth=1000¦Scale=100¦PaperSource=15¦PrintQuality=600¦MediaType=1¦DitherType=10¦PaperKind=Letter¦PrintScaleMode=1

## Sheet AAP006H_MSP430.SchDoc
size 431 x 279 mm; Date: Not shown in title block; ApprovedBy: Not shown in title block; CheckedBy: Not shown in title block; Author: Not shown in title block; CompanyName: Not shown in title block; Engineer: Not shown in title block; Organization: Not shown in title block; Address1: Not shown in title block; Address2: Not shown in title block; Address3: Not shown in title block; Address4: Not shown in title block; DocumentNumber: 8; Revision: Use project parameter SCH_Rev; SheetNumber: 8; SheetTotal: 13; PageSetup: Record=PageOptions¦CenterHorizontal=True¦CenterVertical=True¦PrintScale=1.00¦XCorrection=1.00¦YCorrection=1.00¦PrintKind=0¦BorderSize=5000000¦LeftOffset=0¦BottomOffset=0¦Orientation=2¦PaperLength=1000¦PaperWidth=1000¦Scale=100¦PaperSource=15¦PrintQuality=600¦MediaType=1¦DitherType=10¦PaperKind=Letter¦PrintScaleMode=1

## Sheet AAP006H_IO-Expander.SchDoc
size 431 x 279 mm; Date: Not shown in title block; ApprovedBy: Not shown in title block; CheckedBy: Not shown in title block; Author: Not shown in title block; CompanyName: Not shown in title block; Engineer: Not shown in title block; Organization: Not shown in title block; Address1: Not shown in title block; Address2: Not shown in title block; Address3: Not shown in title block; Address4: Not shown in title block; DocumentNumber: 9; Revision: Use project parameter SCH_Rev; SheetNumber: 9; SheetTotal: 13; PageSetup: Record=PageOptions¦CenterHorizontal=True¦CenterVertical=True¦PrintScale=1.00¦XCorrection=1.00¦YCorrection=1.00¦PrintKind=0¦BorderSize=5000000¦LeftOffset=0¦BottomOffset=0¦Orientation=2¦PaperLength=1000¦PaperWidth=1000¦Scale=100¦PaperSource=15¦PrintQuality=600¦MediaType=1¦DitherType=10¦PaperKind=Letter¦PrintScaleMode=1

## Sheet AAP006H_MainConnector.SchDoc
size 431 x 279 mm; Date: Not shown in title block; ApprovedBy: Not shown in title block; CheckedBy: Not shown in title block; Author: Not shown in title block; CompanyName: Not shown in title block; Engineer: Not shown in title block; Organization: Not shown in title block; Address1: Not shown in title block; Address2: Not shown in title block; Address3: Not shown in title block; Address4: Not shown in title block; DocumentNumber: 10; Revision: Use project parameter SCH_Rev; SheetNumber: 10; SheetTotal: 13; PageSetup: Record=PageOptions¦CenterHorizontal=True¦CenterVertical=True¦PrintScale=1.00¦XCorrection=1.00¦YCorrection=1.00¦PrintKind=0¦BorderSize=5000000¦LeftOffset=0¦BottomOffset=0¦Orientation=2¦PaperLength=1000¦PaperWidth=1000¦Scale=100¦PaperSource=15¦PrintQuality=600¦MediaType=1¦DitherType=10¦PaperKind=Letter¦PrintScaleMode=1

## Sheet AAP006H_PowerSupplies.SchDoc
size 431 x 279 mm; Date: Not shown in title block; ApprovedBy: Not shown in title block; CheckedBy: Not shown in title block; Author: Not shown in title block; CompanyName: Not shown in title block; Engineer: Not shown in title block; Organization: Not shown in title block; Address1: Not shown in title block; Address2: Not shown in title block; Address3: Not shown in title block; Address4: Not shown in title block; DocumentNumber: 11; Revision: Use project parameter SCH_Rev; SheetNumber: 11; SheetTotal: 13; PageSetup: Record=PageOptions¦CenterHorizontal=True¦CenterVertical=True¦PrintScale=1.00¦XCorrection=1.00¦YCorrection=1.00¦PrintKind=0¦BorderSize=5000000¦LeftOffset=0¦BottomOffset=0¦Orientation=2¦PaperLength=1000¦PaperWidth=1000¦Scale=100¦PaperSource=15¦PrintQuality=600¦MediaType=1¦DitherType=10¦PaperKind=Letter¦PrintScaleMode=1
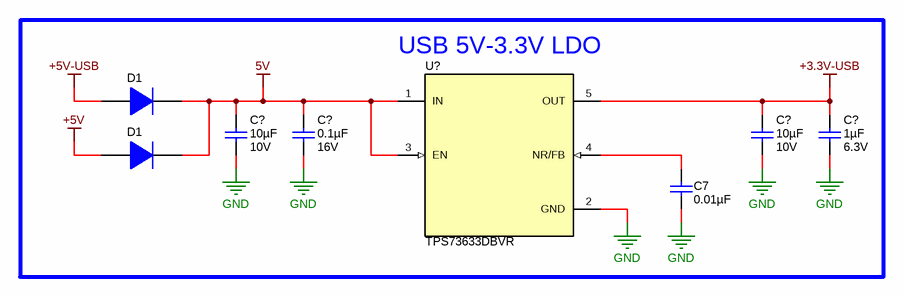
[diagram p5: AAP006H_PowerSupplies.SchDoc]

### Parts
(Parts that share a designator on the sheet are numbered #1, #2 ... from top to bottom, then left to right.)
C7  ValueDisplayed: 0.01µF  [0402L]  (hidden comment: C1005X7R1C103K)
C?#22  ValueDisplayed: 1µF  Value2: 6.3V  [0402]  (hidden comment: C1005X5R0J105M050BB)
C?#23  ValueDisplayed: 10µF  Value2: 10V  [0603]  (hidden comment: C1608X5R1A106M080AC)
C?#24  ValueDisplayed: 0.1µF  Value2: 16V  [0402L]  (hidden comment: GRM155R71C104KA88D)
C?#25  ValueDisplayed: 10µF  Value2: 10V  [0603]  (hidden comment: C1608X5R1A106M080AC)
D1#1  ES2DA-13-F  [SMA]  (value not drawn)
D1#2  ES2DA-13-F  [SMA]  (value not drawn)
U?#13  TPS73633DBVR  [DBV0005A_N]

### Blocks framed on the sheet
USB 5V-3.3V LDO: C7 C?#22-C?#25 D1#1 D1#2 U?#13

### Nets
5V: C?#23.1 C?#24.1 D1#1.1(K) D1#2.1(K) U?#13.1(IN) U?#13.3(EN)
+3.3V-USB: C?#22.2 C?#25.1 U?#13.5(OUT)
+5V: D1#2.2(A)
+5V-USB: D1#1.2(A)
GND: C7.2 C?#22.1 C?#23.2 C?#24.2 C?#25.2 U?#13.2(GND)
NetC7_1: C7.1 U?#13.4(NR/FB)

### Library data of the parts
C7 = C1005X7R1C103K: CAP, CERM, 0.01uF, 16V, +/-10%, X7R, 0402; Manufacturer: TDK; Polarized: N; CompType: Capacitor; U/M: EA; Cap_F: 0.00000001; Tolerance_%: 10; ESR_Ohm: 0.0623; Value1: 0.0623 ohm; VDC_V: 16; TaMin_C: -55; TaMax_C: 125; Cap_Case: 0402
C?#22 = C1005X5R0J105M050BB: CAP, CERM, 1 µF, 6.3 V, +/- 20%, X5R, 0402; Manufacturer: TDK; Polarized: N; CompType: Capacitor; Value: 1uF; U/M: EA; Cap_F: 0.000001; Tolerance_%: 20; ESR_ohm: 0.0079; Value1: 0.0079 ohm; VDC_V: 6.3; TaMin_C: -55; TaMax_C: 85; SizeArea_mm2: 0.5; SizeAreaWB_mm2: 3; SizeX_mm: 1; SizeZ_mm: 0.6; AEC Category: Q200
C?#23 C?#25 = C1608X5R1A106M080AC: CAP, CERM, 10 µF, 10 V, +/- 20%, X5R, 0603; Manufacturer: TDK; Polarized: N; CompType: Capacitor; Value: 10uF; U/M: EA; Cap_F: 0.00001; Tolerance_%: 20; ESR_ohm: 0.0078; Value1: 0.0078 ohm; VDC_V: 10; IRMS_A: 1.85; TaMin_C: -55; TaMax_C: 85; SizeArea_mm2: 1.28; SizeAreaWB_mm2: 4.68; SizeX_mm: 1.6; SizeY_mm: 0.8; SizeZ_mm: 1; AEC Category: Q200
C?#24 = GRM155R71C104KA88D: as C?#5 on sheet AAP006H_USB
D1#1 D1#2 = ES2DA-13-F: Diode, Superfast Rectifier, 200 V, 2 A, SMA; Manufacturer: Diodes Inc.; U/M: EA; Vf_V: 0.92; Value: 200V; Value1: 2A; Value2: 0.92V; Io_A: 2; Vr_V: 200; TJmax_C: 150; RJC_CperW: 20; SizeAreaWB_mm2: 37.3428; SizeArea_mm2: 16.3228; SizeX_mm: 5.59; SizeY_mm: 2.92; SizeZ_mm: 2.87; AEC Category: Q101
U?#13 = TPS73633DBVR: Cap-Free, NMOS, 400mA Low-Dropout Regulator with Reverse Current Protection, DBV0005A (SOT-5); Alternate Manufacturer: Texas Instruments; Alternate PartNumber: TPS73633DBVT; SymbolCreator: a0411947; CompType: IC; U/M: EA; SizeArea_mm2: 8.12; SizeAreaWB_mm2: 14.82; SizeX_mm: 2.8; SizeY_mm: 2.9; SizeZ_mm: 1.45

## Sheet AAP006H_StandoffHardware.SchDoc
size 431 x 279 mm; Date: Not shown in title block; ApprovedBy: Not shown in title block; CheckedBy: Not shown in title block; Author: Not shown in title block; CompanyName: Not shown in title block; Engineer: Not shown in title block; Organization: Not shown in title block; Address1: Not shown in title block; Address2: Not shown in title block; Address3: Not shown in title block; Address4: Not shown in title block; DocumentNumber: 12; Revision: Use project parameter SCH_Rev; SheetNumber: 12; SheetTotal: 13; PageSetup: Record=PageOptions¦CenterHorizontal=True¦CenterVertical=True¦PrintScale=1.00¦XCorrection=1.00¦YCorrection=1.00¦PrintKind=0¦BorderSize=5000000¦LeftOffset=0¦BottomOffset=0¦Orientation=2¦PaperLength=1000¦PaperWidth=1000¦Scale=100¦PaperSource=15¦PrintQuality=600¦MediaType=1¦DitherType=10¦PaperKind=Letter¦PrintScaleMode=1

## Sheet AAP006H_EVM_Hardware.SchDoc
size 431 x 279 mm; Date: Not shown in title block; ApprovedBy: Not shown in title block; CheckedBy: Not shown in title block; Author: Not shown in title block; CompanyName: Not shown in title block; Engineer: Not shown in title block; Organization: Not shown in title block; Address1: Not shown in title block; Address2: Not shown in title block; Address3: Not shown in title block; Address4: Not shown in title block; DocumentNumber: 13; Revision: Use project parameter SCH_Rev; SheetNumber: 13; SheetTotal: 13; PageSetup: Record=PageOptions¦CenterHorizontal=True¦CenterVertical=True¦PrintScale=1.00¦XCorrection=1.00¦YCorrection=1.00¦PrintKind=0¦BorderSize=5000000¦LeftOffset=0¦BottomOffset=0¦Orientation=2¦PaperLength=1000¦PaperWidth=1000¦Scale=100¦PaperSource=15¦PrintQuality=600¦MediaType=1¦DitherType=10¦PaperKind=Letter¦PrintScaleMode=1
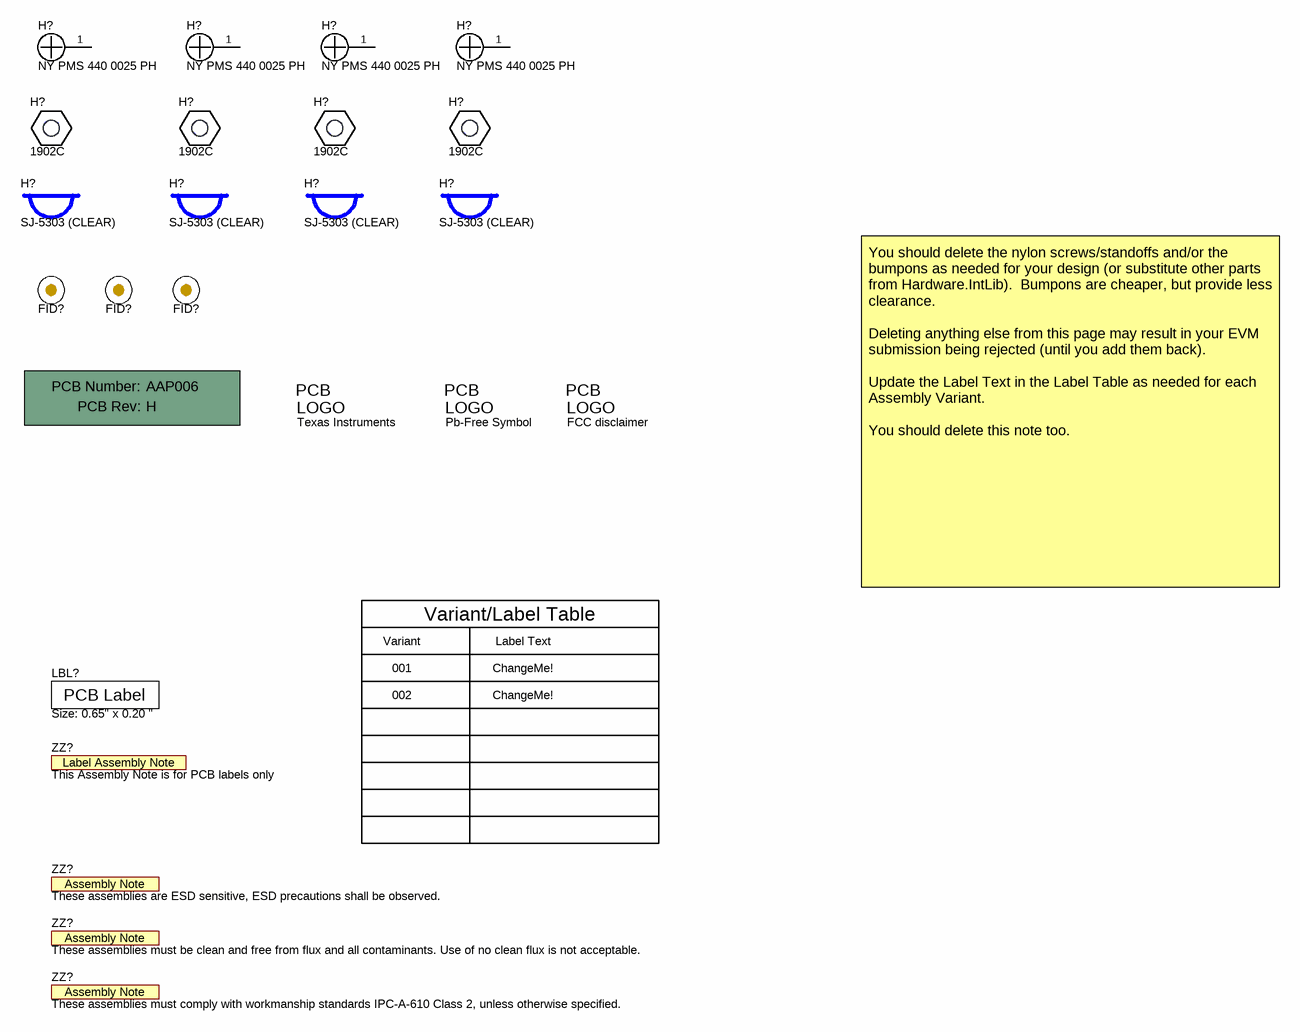
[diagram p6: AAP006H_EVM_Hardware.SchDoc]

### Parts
!PCB?  Printed Circuit Board  (value not drawn)  (mechanical)
FID1  Fiducial  [Fiducial10-20]  (value not drawn)
FID2  Fiducial  [Fiducial10-20]  (value not drawn)
FID3  Fiducial  [Fiducial10-20]  (value not drawn)
H1  NY PMS 440 0025 PH  [NY PMS 440 0025 PH]
H2  NY PMS 440 0025 PH  [NY PMS 440 0025 PH]
H3  NY PMS 440 0025 PH  [NY PMS 440 0025 PH]
H4  NY PMS 440 0025 PH  [NY PMS 440 0025 PH]
H5  1902C  [Keystone_1902C]
H6  1902C  [Keystone_1902C]
H7  1902C  [Keystone_1902C]
H8  1902C  [Keystone_1902C]
H9  SJ-5303 (CLEAR)  [Bumpon_SJ5003Transparent]
H10  SJ-5303 (CLEAR)  [Bumpon_SJ5003Transparent]
H11  SJ-5303 (CLEAR)  [Bumpon_SJ5003Transparent]
H12  SJ-5303 (CLEAR)  [Bumpon_SJ5003Transparent]
LBL1  Size: 0.65" x 0.20 "  [Label_650x200]
Logo1  Texas Instruments  [TI_Stacked_Overlay_Small]  (no BOM)
Logo2  Pb-Free Symbol  [Pb-Free_Overlay_Small]  (no BOM)
Logo3  FCC disclaimer  [FCC_disclaimer]  (no BOM)
ZZ1  This Assembly Note is for PCB labels only  [AssemblyNoteLabel]  (no BOM)
ZZ2  These assemblies are ESD sensitive, ESD precautions shall be observed.  [AssemblyNote]  (no BOM)
ZZ3  These assemblies must be clean and free from flux and all contaminants. Use of no clean flux is not acceptable.  [AssemblyNote]  (no BOM)
ZZ4  These assemblies must comply with workmanship standards IPC-A-610 Class 2, unless otherwise specified.  [AssemblyNote]  (no BOM)

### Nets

Not connected (* = marked no-connect by the designer): H1 1; H2 1; H3 1; H4 1

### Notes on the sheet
- Variant
- Variant/Label Table
- Label Text
- You should delete the nylon screws/standoffs and/or the bumpons as needed for your design (or substitute other parts from Hardware.IntLib).  Bumpons are cheaper, but provide less clearance.
  Deleting anything else from this page may result in your EVM submission being rejected (until you add them back).
  Update the Label Text in the Label Table as needed for each Assembly Variant.
  You should delete this note too.
- 001
- 002
- ChangeMe!

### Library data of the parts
!PCB? = PCB: Manufacturer: Any; PartNumber: AAP006; SymbolCreator: a0412235
FID1-FID3 = Fiducial: Fiducial mark.  There is nothing to buy or mount.; SymbolCreator: codlsc
H1-H4 = NY PMS 440 0025 PH: Machine Screw, Round, #4-40 x 1/4, Nylon, Philips panhead; Manufacturer: B&F Fastener Supply; CompType: Hardware; SymbolCreator: codlsc; U/M: EA
H5-H8 = 1902C: Standoff, Hex, 0.5"L #4-40 Nylon; Manufacturer: Keystone; CompType: Hardware
H9-H12 = SJ-5303 (CLEAR): Bumpon, Hemisphere, 0.44 X 0.20, Clear; Manufacturer: 3M; SymbolCreator: a0412235
LBL1 = THT-14-423-10: Thermal Transfer Printable Labels, 0.650" W x 0.200" H - 10,000 per roll; Manufacturer: Brady; SymbolCreator: a0412235; CompType: Label
Logo1 = TI_Logo: Texas Instrument Corporate Signature; SymbolCreator: codlsc
Logo2 = Pb-Free: SymbolCreator: a0412235
Logo3 = FCC_disclaimer: SymbolCreator: codlsc
ZZ1 = AssemblyNoteLabel: SymbolCreator: a0412235
ZZ2-ZZ4 = AssemblyNote: SymbolCreator: codlsc

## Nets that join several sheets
+3.3V-USB: AAP006H_USB (16 pins), AAP006H_PowerSupplies (C?#22.2 C?#25.1 U?#13.5)
+5V-USB: AAP006H_USB (FB?#1.2 R?#9.1), AAP006H_PowerSupplies (D1#1.2)
GND: AAP006H_USB (50 pins), AAP006H_PowerSupplies (6 pins)

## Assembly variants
001: not fitted FID1 FID2 FID3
